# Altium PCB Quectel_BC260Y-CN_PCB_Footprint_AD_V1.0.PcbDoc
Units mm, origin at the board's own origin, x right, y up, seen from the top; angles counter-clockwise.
Board outline 152.4 x 101.6 mm, 2 copper layers (Top Layer, Bottom Layer); 1 components, 0 nets, 58 pads, 0 vias.
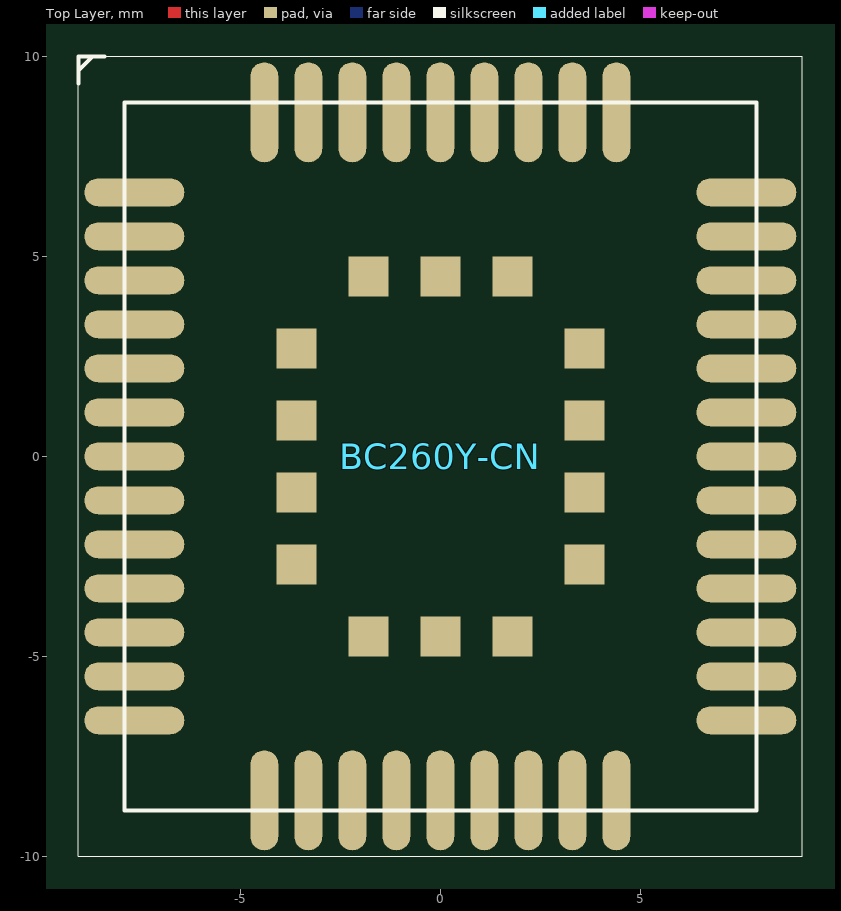
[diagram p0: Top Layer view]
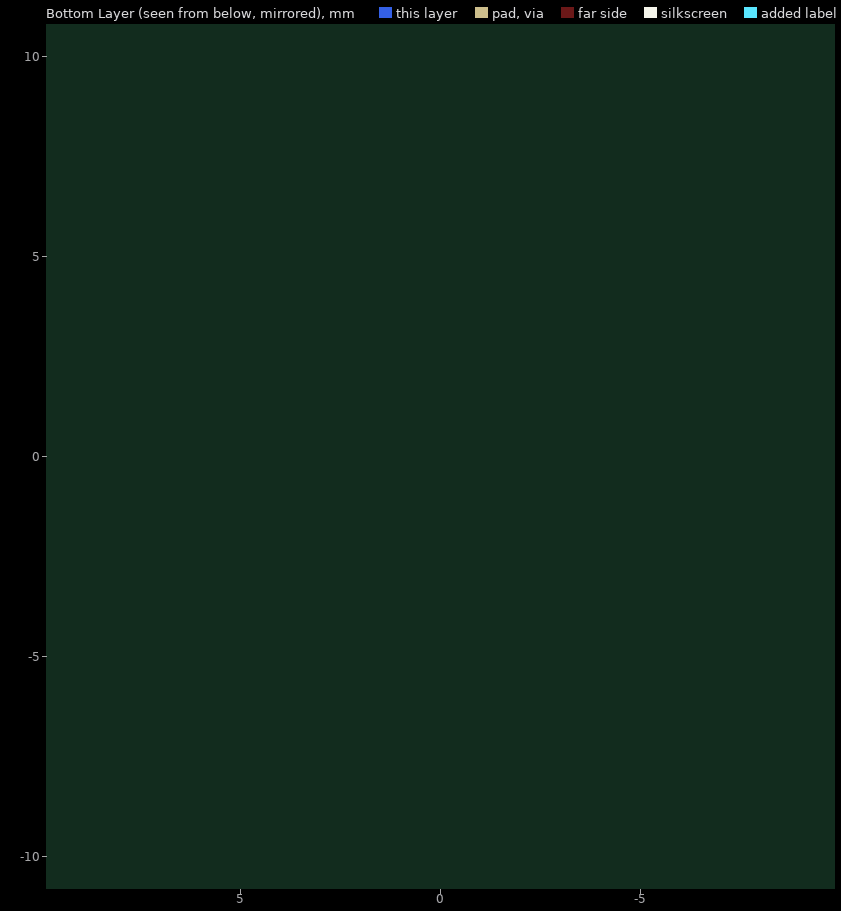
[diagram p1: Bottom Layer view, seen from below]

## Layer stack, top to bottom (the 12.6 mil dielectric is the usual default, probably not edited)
Top Layer: signal copper 0.0356
Dielectric: dielectric 0.32, FR-4, Dk 4.8
Bottom Layer: signal copper 0.0356

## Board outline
-46.482,-48.895 105.918,-48.895 105.918,52.705 -46.482,52.705

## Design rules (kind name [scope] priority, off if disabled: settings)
Clearance [All] p1: gap=0.254
PolygonConnect [All] p1: connectstyle=Relief reliefconductorwidth=0.254 reliefentries=4 polygonreliefangle="90 Angle" airgapwidth=0.254
RoutingVias [All] p1: holewidth=0.711 width=1.27 viastyle="Through Hole" minholewidth=0.711 minwidth=1.27 maxholewidth=0.711 maxwidth=1.27
SolderMaskExpansion [All] p1: expansion=0.102
Width [All] p1: maxlimit=0.254 minlimit=0.254 preferedwidth=0.254
28 further rules are at their usual default settings.

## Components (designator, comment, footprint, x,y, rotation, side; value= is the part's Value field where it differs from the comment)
BC260Y-CN "Comment" BC260Y-CN 0,0 r0 top

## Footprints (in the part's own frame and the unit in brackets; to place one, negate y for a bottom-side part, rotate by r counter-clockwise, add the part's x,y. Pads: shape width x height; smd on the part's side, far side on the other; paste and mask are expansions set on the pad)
BC260Y-CN [mm]
  oval 2.5x0.7 smd mask+0.05: 1(-7.65,6.6) 2(-7.65,5.5) 3(-7.65,4.4) 4(-7.65,3.3) 5(-7.65,2.2) 6(-7.65,1.1) 7(-7.65,0) 8(-7.65,-1.1) 9(-7.65,-2.2) 10(-7.65,-3.3) 11(-7.65,-4.4) 12(-7.65,-5.5) 13(-7.65,-6.6) 23(7.65,-6.6) 24(7.65,-5.5) 25(7.65,-4.4) 26(7.65,-3.3) 27(7.65,-2.2) 28(7.65,-1.1) 29(7.65,0) 30(7.65,1.1) 31(7.65,2.2) 32(7.65,3.3) 33(7.65,4.4) 34(7.65,5.5) 35(7.65,6.6)
  oval 0.7x2.5 smd mask+0.05: 14(-4.4,-8.6) 15(-3.3,-8.6) 16(-2.2,-8.6) 17(-1.1,-8.6) 18(0,-8.6) 19(1.1,-8.6) 20(2.2,-8.6) 21(3.3,-8.6) 22(4.4,-8.6) 36(4.4,8.6) 37(3.3,8.6) 38(2.2,8.6) 39(1.1,8.6) 40(0,8.6) 41(-1.1,8.6) 42(-2.2,8.6) 43(-3.3,8.6) 44(-4.4,8.6)
  rect 1x1 smd mask+0.05: 45(-3.6,2.7) 46(-3.6,0.9) 47(-3.6,-0.9) 48(-3.6,-2.7) 49(-1.8,-4.5) 50(0,-4.5) 51(1.8,-4.5) 52(3.6,-2.7) 53(3.6,-0.9) 54(3.6,0.9) 55(3.6,2.7) 56(1.8,4.5) 57(0,4.5) 58(-1.8,4.5)
  silkscreen extent -9.05,-10 9.05,10

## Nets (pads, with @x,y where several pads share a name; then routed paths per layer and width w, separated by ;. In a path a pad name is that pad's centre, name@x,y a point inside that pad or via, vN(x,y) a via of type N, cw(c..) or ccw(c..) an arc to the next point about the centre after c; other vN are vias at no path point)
pads on no net: BC260Y-CN.1 BC260Y-CN.2 BC260Y-CN.3 BC260Y-CN.4 BC260Y-CN.5 BC260Y-CN.6 BC260Y-CN.7 BC260Y-CN.8 BC260Y-CN.9 BC260Y-CN.10 BC260Y-CN.11 BC260Y-CN.12 BC260Y-CN.13 BC260Y-CN.14 BC260Y-CN.15 BC260Y-CN.16 BC260Y-CN.17 BC260Y-CN.18 BC260Y-CN.19 BC260Y-CN.20 BC260Y-CN.21 BC260Y-CN.22 BC260Y-CN.23 BC260Y-CN.24 BC260Y-CN.25 BC260Y-CN.26 BC260Y-CN.27 BC260Y-CN.28 BC260Y-CN.29 BC260Y-CN.30 BC260Y-CN.31 BC260Y-CN.32 BC260Y-CN.33 BC260Y-CN.34 BC260Y-CN.35 BC260Y-CN.36 BC260Y-CN.37 BC260Y-CN.38 BC260Y-CN.39 BC260Y-CN.40 BC260Y-CN.41 BC260Y-CN.42 BC260Y-CN.43 BC260Y-CN.44 BC260Y-CN.45 BC260Y-CN.46 BC260Y-CN.47 BC260Y-CN.48 BC260Y-CN.49 BC260Y-CN.50 BC260Y-CN.51 BC260Y-CN.52 BC260Y-CN.53 BC260Y-CN.54 BC260Y-CN.55 BC260Y-CN.56 BC260Y-CN.57 BC260Y-CN.58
